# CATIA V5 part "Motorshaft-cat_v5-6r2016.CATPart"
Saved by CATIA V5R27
Part number: Motorshaft
Bounding box of the stored display mesh (mm): x -7.25 to 7.25, y -240 to 240, z -7.25 to 7.25
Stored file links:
  E:\_Deepak\2017_Deepak\CATIA\Resources\Tutorial Files\Tutorials\c12_catia_v5_6r2015_tut\c12Tut1\Motorshaft-cat_v5-6r2016.CATPart
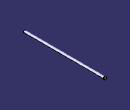
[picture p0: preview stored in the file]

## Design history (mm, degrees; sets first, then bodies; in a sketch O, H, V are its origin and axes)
Body1 (main body)
  Sketch1 on zx-plane, origin (0, 0, 0), H (-1, 0, 0), V (0, 0, 1)
    circle A1 centre (0, 0) radius 7.25
    radius A1 = 7.25
  Pad1: profile Sketch1, direction (0, 1, 0), length 240, mirrored extent
  Sketch2 on yz-plane, origin (0, 0, 0), H (0, 1, 0), V (0, 0, 1)
    line L1 (233.2, 6) -> (235, 6)
    line L2 (235, 6) -> (235, 7.25)
    line L3 (235, 7.25) -> (233.2, 7.25)
    line L4 (233.2, 7.25) -> (233.2, 6)
    reference projected line E1 (240, 7.25) -> (240, -7.25) from edge of Pad1
    reference projected line E2 through (0, 0) direction (1, 0) from axis of face of Pad1 from Sketch1.A1
    distance E1 L2 = 5
    distance H L3 = 7.25
    length L1 = 1.8
    distance L1 E2 = 6
    horizontal: L1 H, L3 H
    vertical: L2 V, L4 V
  Groove1: profile Sketch2, axis axis of face of Pad1, angle 360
